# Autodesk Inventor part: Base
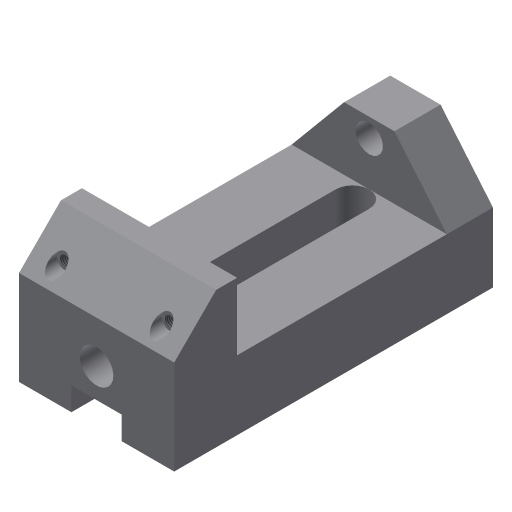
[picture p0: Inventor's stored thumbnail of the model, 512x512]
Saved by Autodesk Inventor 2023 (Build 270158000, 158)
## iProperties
Shininess: 77.0
Length Units: 11269
Angle Units: 11279
Time Units: 11290
Mass Units: 11283
Length Display Precision: 3
Angle Display Precision: 2
Created: 2002-02
Part Number: Base
Document SubType Name: Modeling
Designer: ***
Density: 1 g/cm^3
Material: Generic
Appearance: Default
Density: 0.0
Volumn: 0.0
Area: 0.0
PropertySet Name: Model Information
Control State: 0
Master: False
Checked Out: False
Author: ***
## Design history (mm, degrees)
sketch "Sketch2"
  geometry: L1 (-63.961, -4.254)-(-63.961, -37.254); L2 (-63.961, -37.254)-(88.039, -37.254); L3 (88.039, -37.254)-(88.039, 7.746); L4 (88.039, 7.746)-(68.039, 27.746); L5 (68.039, 27.746)-(58.039, 27.746); L6 (58.039, 27.746)-(58.039, -4.254); L7 (58.039, -4.254)-(-63.961, -4.254)
  constraints: 14 end point, 4 parallel, 1 perpendicular, 1 vertical
  dimensions: "d7" = 10 distance of L4.end L5.end; "d8" = 135 deg angle of L3 L4; "d9" = 33 distance of L1.start L1.end; "d10" = 152 distance of L1.end L2.end; "d11" = 65 distance between parallel lines of L5 L2; "d21" = 30 distance between parallel lines of L3 L6
extrude "Extrusion1" new body sketch "Sketch2" stored distance "d13" = 74; taper "d14" = 0 deg
sketch "Sketch3"
  geometry: L1 (0, 74)-(0, 0) reference; L2 (0, 0)-(-30, 25); L3 (-30, 25)-(-30, 49); L4 (-30, 49)-(0, 74); C1 r 6.5 at (-21, 37)
  constraints: 6 end point, 1 centre point, 1 equal length, 1 parallel
  dimensions: "d15" = 24 distance of L2.end L3.end; "d16" = 30 distance between parallel lines of L3 L1; "d17" = 13 diameter of C1; "d18" = 9 distance from line of L3 C1.centre
extrude "Extrusion2" join sketch "Sketch3" distance "d19" = 22; taper "d20" = 0 deg
sketch "Sketch4"
  geometry: L1 (0, 0)-(0, 74) reference; L2 (0, 0)-(45, 0) reference; C1 r 8 at (25, 37)
  constraints: 1 centre point
  dimensions: "d22" = 16 diameter of C1; "d23" = 25 distance from line of L1 C1.centre; "d24" = 37 distance from line of L2 C1.centre
extrude "Extrusion3" cut sketch "Sketch4" distance "d25" = 13; taper "d26" = 0 deg
sketch "Sketch5"
  geometry: L1 (45, 74)-(0, 74) reference; L2 (65, 0)-(65, 74) reference; 1 further point
  dimensions: "d27" = 12 distance from line of point (51, 62) L1; "d28" = 14 distance from line of L2 point (51, 62)
hole "Hole1" sketch "Sketch5" at (51, 62) diameter "d29" = 4.917; stored, may be unused: countersink angle "d33" = 82 deg, drill point angle "d35" = 0 deg; dims "d30" = 12, "d31" = 8, "d32" = 10, "d34" = 45
mirror "Mirror1"
sketch "Sketch6"
  geometry: L1 (100, 0)-(100, 74) reference; L2 (100, 74)-(0, 74) reference; L3 (14, 45)-(92, 45); L4 (92, 29)-(14, 29); A1 r 8 centre (92, 37) between (92, 29) and (92, 45); A2 r 8 centre (14, 37) between (14, 45) and (14, 29)
  constraints: 4 end point, 4 point on circle, 4 tangent, 2 centre point, 1 horizontal, 1 parallel
  dimensions: "d36" = 8 radius of A2; "d37" = 78 distance of L4.start L4.end; "d38" = 8 distance from line of L1 A1.centre; "d39" = 37 distance from line of L2 A2.centre
extrude "Extrusion4" cut sketch "Sketch6" extent not by distance; stored distance "d40" = 13; taper "d41" = 0 deg
sketch "Sketch7"
  geometry: L1 (45, 74)-(0, 74) reference; L2 (11, 49)-(0, 49); L3 (0, 49)-(0, 25); L4 (0, 25)-(11, 25); L5 (11, 25)-(11, 49); L6 (0, 0)-(45, 0) reference; L7 (0, 0)-(0, 74) reference
  constraints: 8 end point, 2 parallel, 1 collinear, 1 horizontal, 1 perpendicular
  dimensions: "d47" = 11 distance of L3.end L4.end; "d48" = 25 distance between parallel lines of L6 L4; "d49" = 24 distance of L2.end L3.end
extrude "Extrusion5" cut sketch "Sketch7" extent not by distance; stored distance "d45" = 13; taper "d46" = 0 deg
body "Solid1"
